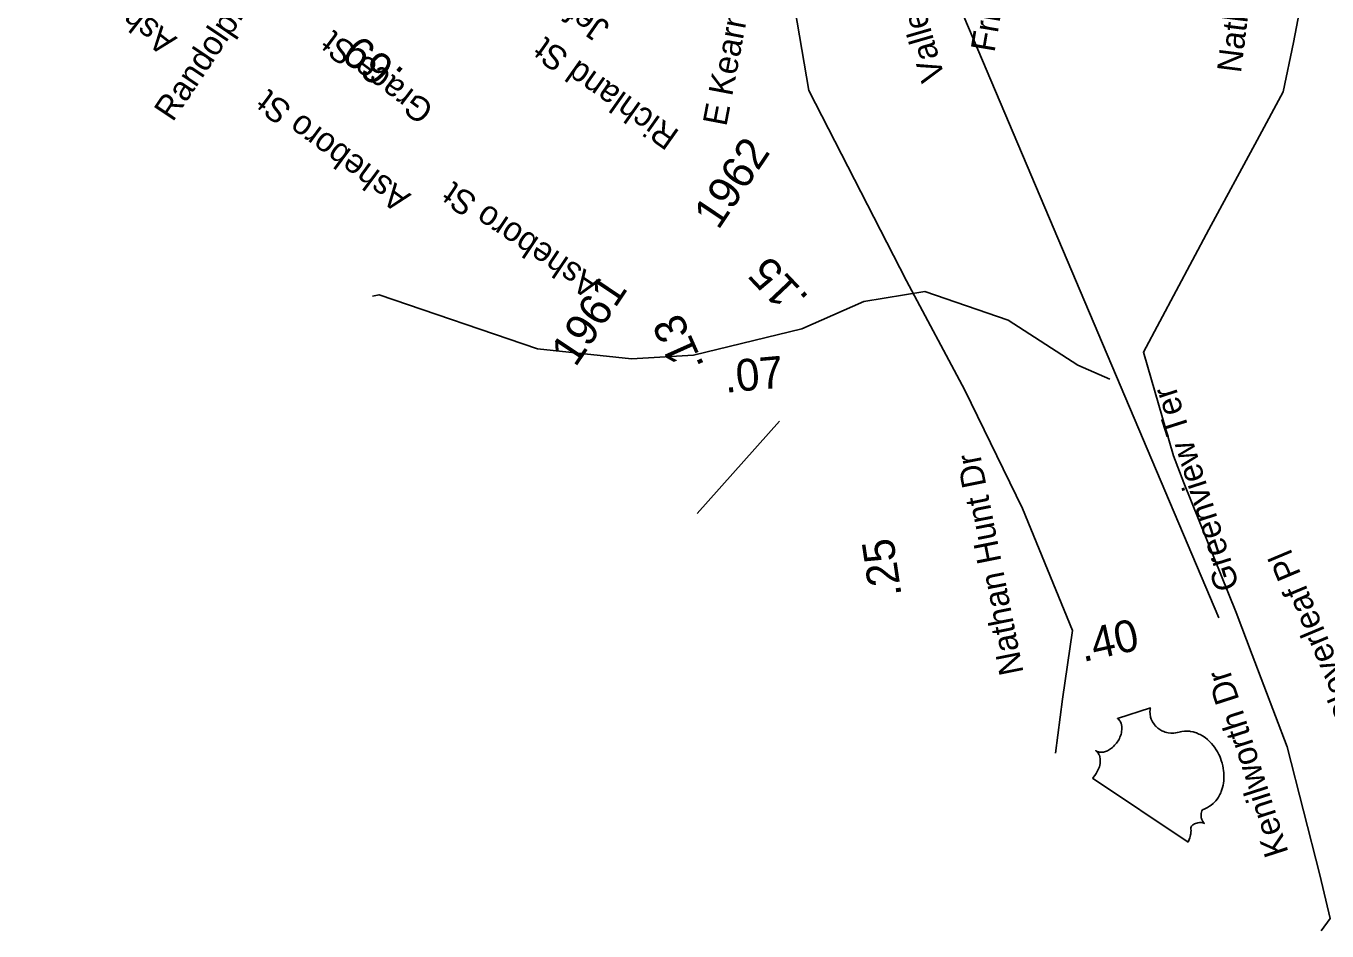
# Model space of a CAD drawing. Extents: x 1716282 to 1717158, y 799307 to 801078.
# Drawn here: x 1716606.6 to 1716680.6, y 799334.3 to 799385.8 of the extents above; entities that cross this region are included whole.
import ezdxf

# ---------------------------------------------------------------- set-up
doc = ezdxf.new("R2010")
doc.units = 0
for name, color, linetype in [('Exist Hydrographic Misc Water Feature', 7, 'Continuous'), ('Exist Road Non-System Type 51 Label', 7, 'Continuous'), ('Exist Road Primary US Mileage Hundredths English Label', 7, 'Continuous'), ('Exist Road Primary US Shield CELL', 7, 'Continuous'), ('Exist Road Primary US Structure Pipe Number Label', 7, 'Continuous'), ('Exist Road Secondary Mileage Hundredths English Label', 7, 'Continuous'), ('Exist Road Secondary Mileage Tenths English Label', 7, 'Continuous'), ('Exist Road Secondary Type 51 Number Label', 7, 'Continuous'), ('Exist Utilities Electrical Transmission Line', 7, 'Continuous')]:
    doc.layers.add(name, color=color, linetype=linetype)

msp = doc.modelspace()

# ---------------------------------------------------------------- linework, layer by layer
at = {"layer": 'Exist Hydrographic Misc Water Feature'}
msp.add_lwpolyline([(1716668.244, 799365.706), (1716666.424, 799366.506), (1716662.465, 799369.068), (1716657.731, 799370.684), (1716654.264, 799370.126), (1716650.742, 799368.575), (1716644.584, 799367.077), (1716641.061, 799366.854), (1716635.716, 799367.43), (1716626.717, 799370.505), (1716626.336, 799370.431)], dxfattribs=at)
at = {"layer": 'Exist Road Primary US Shield CELL'}
msp.add_line((1716667.27, 799343.034), (1716672.705, 799339.396), dxfattribs=at)
msp.add_lwpolyline([(1716672.705, 799339.396), (1716672.727, 799339.445), (1716672.765, 799339.536), (1716672.798, 799339.629), (1716672.822, 799339.717), (1716672.839, 799339.796), (1716672.85, 799339.864), (1716672.86, 799339.96), (1716672.863, 799340.045), (1716672.861, 799340.125), (1716672.859, 799340.211), (1716672.877, 799340.26), (1716672.897, 799340.292), (1716672.926, 799340.328), (1716672.968, 799340.366), (1716673.008, 799340.394), (1716673.056, 799340.421), (1716673.122, 799340.452), (1716673.194, 799340.474), (1716673.259, 799340.488), (1716673.34, 799340.498), (1716673.399, 799340.5), (1716673.463, 799340.497), (1716673.532, 799340.485), (1716673.625, 799340.451), (1716673.572, 799340.508), (1716673.54, 799340.554), (1716673.517, 799340.592), (1716673.476, 799340.684), (1716673.465, 799340.725), (1716673.45, 799340.779), (1716673.438, 799340.85), (1716673.433, 799340.906), (1716673.434, 799340.974), (1716673.439, 799341.022), (1716673.455, 799341.097), (1716673.481, 799341.163), (1716673.525, 799341.222), (1716673.549, 799341.243), (1716673.604, 799341.272), (1716673.81, 799341.364), (1716673.919, 799341.427), (1716674.017, 799341.495), (1716674.116, 799341.577), (1716674.202, 799341.661), (1716674.278, 799341.746), (1716674.352, 799341.84), (1716674.419, 799341.94), (1716674.464, 799342.017), (1716674.507, 799342.098), (1716674.55, 799342.188), (1716674.582, 799342.266), (1716674.656, 799342.49), (1716674.689, 799342.633), (1716674.71, 799342.746), (1716674.725, 799342.879), (1716674.736, 799343.04), (1716674.736, 799343.211), (1716674.729, 799343.341), (1716674.719, 799343.435), (1716674.697, 799343.594), (1716674.672, 799343.722), (1716674.631, 799343.886), (1716674.586, 799344.03), (1716674.538, 799344.159), (1716674.494, 799344.267), (1716674.45, 799344.363), (1716674.371, 799344.514), (1716674.3, 799344.636), (1716674.193, 799344.793), (1716674.115, 799344.891), (1716674.024, 799345.002), (1716673.94, 799345.089), (1716673.794, 799345.226), (1716673.66, 799345.331), (1716673.512, 799345.43), (1716673.383, 799345.502), (1716673.314, 799345.535), (1716673.173, 799345.595), (1716673.107, 799345.617), (1716672.978, 799345.656), (1716672.838, 799345.684), (1716672.774, 799345.692), (1716672.7, 799345.698), (1716672.629, 799345.702), (1716672.557, 799345.702), (1716672.492, 799345.699), (1716672.345, 799345.681), (1716672.263, 799345.665), (1716672.197, 799345.647), (1716672.077, 799345.613), (1716671.987, 799345.596), (1716671.888, 799345.585), (1716671.724, 799345.586), (1716671.573, 799345.602), (1716671.486, 799345.62), (1716671.399, 799345.645), (1716671.327, 799345.67), (1716671.271, 799345.694), (1716671.208, 799345.723), (1716671.15, 799345.754), (1716671.091, 799345.789), (1716671.038, 799345.825), (1716670.986, 799345.865), (1716670.881, 799345.956), (1716670.834, 799346.006), (1716670.782, 799346.068), (1716670.705, 799346.176), (1716670.672, 799346.233), (1716670.637, 799346.303), (1716670.608, 799346.371), (1716670.581, 799346.443), (1716670.566, 799346.497), (1716670.552, 799346.557), (1716670.541, 799346.619), (1716670.533, 799346.68), (1716670.53, 799346.809), (1716670.534, 799346.886), (1716670.546, 799346.979), (1716670.555, 799347.016), (1716668.678, 799346.419), (1716668.715, 799346.392), (1716668.756, 799346.356), (1716668.799, 799346.309), (1716668.834, 799346.256), (1716668.865, 799346.203), (1716668.889, 799346.142), (1716668.915, 799346.048), (1716668.929, 799345.958), (1716668.935, 799345.886), (1716668.932, 799345.795), (1716668.921, 799345.687), (1716668.906, 799345.608), (1716668.885, 799345.522), (1716668.853, 799345.431), (1716668.827, 799345.364), (1716668.791, 799345.284), (1716668.754, 799345.213), (1716668.715, 799345.146), (1716668.669, 799345.076), (1716668.63, 799345.02), (1716668.578, 799344.954), (1716668.523, 799344.893), (1716668.467, 799344.834), (1716668.406, 799344.777), (1716668.342, 799344.725), (1716668.29, 799344.686), (1716668.235, 799344.651), (1716668.115, 799344.583), (1716667.997, 799344.536), (1716667.949, 799344.522), (1716667.892, 799344.508), (1716667.786, 799344.496), (1716667.72, 799344.496), (1716667.648, 799344.506), (1716667.599, 799344.516), (1716667.556, 799344.531), (1716667.515, 799344.55), (1716667.453, 799344.585), (1716667.52, 799344.532), (1716667.549, 799344.502), (1716667.608, 799344.423), (1716667.631, 799344.379), (1716667.654, 799344.331), (1716667.685, 799344.232), (1716667.704, 799344.121), (1716667.707, 799344.049), (1716667.705, 799343.962), (1716667.695, 799343.858), (1716667.677, 799343.769), (1716667.653, 799343.677), (1716667.625, 799343.598), (1716667.556, 799343.434), (1716667.478, 799343.296), (1716667.394, 799343.176), (1716667.298, 799343.061), (1716667.27, 799343.034)], dxfattribs=at)
at = {"layer": 'Exist Road Primary US Structure Pipe Number Label'}
msp.add_line((1716674.439, 799352.144), (1716658.834, 799388.944), dxfattribs=at)
at = {"layer": 'Exist Road Secondary Type 51 Number Label'}
msp.add_line((1716649.466, 799363.314), (1716644.795, 799358.076), dxfattribs=at)
at = {"layer": 'Exist Utilities Electrical Transmission Line'}
for points in [[(1716665.164, 799344.443), (1716665.563, 799347.513), (1716666.118, 799351.428), (1716663.285, 799358.348), (1716660.01, 799365.081), (1716656.683, 799371.286), (1716651.135, 799382.119), (1716649.283, 799393.013), (1716647.919, 799400.679), (1716645.991, 799411.31), (1716644.572, 799419.966), (1716643.666, 799425.239), (1716641.374, 799438.762), (1716638.601, 799455.36), (1716638.051, 799459.861), (1716636.812, 799466.701), (1716635.068, 799476.572), (1716633.977, 799482.851), (1716632.367, 799492.558)], [(1716680.26, 799334.339), (1716680.764, 799335.057), (1716680.185, 799337.535), (1716678.331, 799344.799), (1716676.348, 799350.042), (1716675.432, 799352.434), (1716672.456, 799359.805), (1716671.861, 799361.346), (1716670.155, 799367.243), (1716673.875, 799374.217), (1716676.633, 799379.291), (1716678.11, 799382.043), (1716678.698, 799384.843), (1716679.28, 799387.925), (1716679.571, 799389.979), (1716679.706, 799392.689), (1716679.774, 799395.79), (1716679.635, 799399.371), (1716678.984, 799410.108), (1716678.759, 799417.692), (1716679.055, 799422.002), (1716682.293, 799426.601)]]:
    msp.add_lwpolyline(points, dxfattribs=at)

# ---------------------------------------------------------------- texts
at = {"layer": 'Exist Road Non-System Type 51 Label'}
for s, rotation, p in [('Nathan Hunt Dr', 82.87203, (1716675.7, 799383.072)), ('Valley Ridge Dr', 106.12958, (1716658.886, 799382.837)), ('Friddle Dr', 80.39387, (1716661.689, 799384.241)), ('Asheboro St', 142.24786, (1716615.288, 799385.094)), ('Jefferson St', 145.31381, (1716639.907, 799385.878)), ('E Kearns Ave', 79.20571, (1716646.452, 799380.033)), ('Randolph St', 56.20506, (1716614.986, 799380.282)), ('Grace St', 142.94811, (1716629.917, 799381.204)), ('Richland St', 144.76889, (1716643.853, 799379.775)), ('Asheboro St', 143.45944, (1716628.581, 799376.187)), ('Asheboro St', 146.20506, (1716639.363, 799371.338)), ('Greenview Ter', 107.7088, (1716675.625, 799353.917)), ('Nathan Hunt Dr', 101.22165, (1716663.352, 799349.024)), ('NW Cloverleaf Pl', 112.81248, (1716683.938, 799343.197)), ('Kenilworth Dr', 107.85984, (1716678.419, 799338.805))]:
    msp.add_text(s, height=1.3775, rotation=rotation, dxfattribs=at).set_placement(p)
at = {"layer": 'Exist Road Primary US Mileage Hundredths English Label'}
msp.add_text('.40', height=1.8125, rotation=12.41485, dxfattribs=at).set_placement((1716666.725, 799349.623))
at = {"layer": 'Exist Road Secondary Mileage Hundredths English Label'}
msp.add_text('.07', height=1.8125, rotation=5.28181, dxfattribs=at).set_placement((1716646.403, 799364.929))
at = {"layer": 'Exist Road Secondary Mileage Tenths English Label'}
for s, rotation, p in [('.69', 140.27059, (1716628.221, 799383.208)), ('.15', 133.37829, (1716651.201, 799370.367)), ('.13', 114.06447, (1716645.222, 799366.474)), ('.25', 98.48899, (1716656.421, 799353.414))]:
    msp.add_text(s, height=1.8125, rotation=rotation, dxfattribs=at).set_placement(p)
at = {"layer": 'Exist Road Secondary Type 51 Number Label'}
for s, p in [('1962', (1716645.992, 799374.14)), ('1961', (1716637.877, 799366.34))]:
    msp.add_text(s, height=1.8125, rotation=56.20506, dxfattribs=at).set_placement(p)

doc.saveas('drawing.dxf')
